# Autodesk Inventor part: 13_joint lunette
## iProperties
Created: 2000-12
Part Number: 13_joint lunette
Material: Par défaut
Document SubType Name: Modélisation
Designer: Administrateur
Control State: 0
Master: False
Checked Out: False
Shininess: 20.0
Length Units: 11269
Angle Units: 11279
Time Units: 11290
Mass Units: 11283
Length Display Precision: 3
Angle Display Precision: 2
Density: 0.0
Volumn: 0.0
Area: 0.0
PropertySet Name: Model Information
Author: Administrateur
